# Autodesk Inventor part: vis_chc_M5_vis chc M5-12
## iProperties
Shininess: 64.0
Length Units: 11269
Angle Units: 11279
Time Units: 11290
Mass Units: 11283
Length Display Precision: 3
Angle Display Precision: 2
Compacted: True
Part Number: vis_chc_M5_vis chc M5-12
Document SubType Name: Modeling
Created: 2006-01
Material: Par défaut
Designer: riri
Density: 0.0
Volumn: 0.0
Area: 0.0
PropertySet Name: Model Information
Control State: 0
Master: False
Checked Out: False
Author: riri
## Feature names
1. Base1
